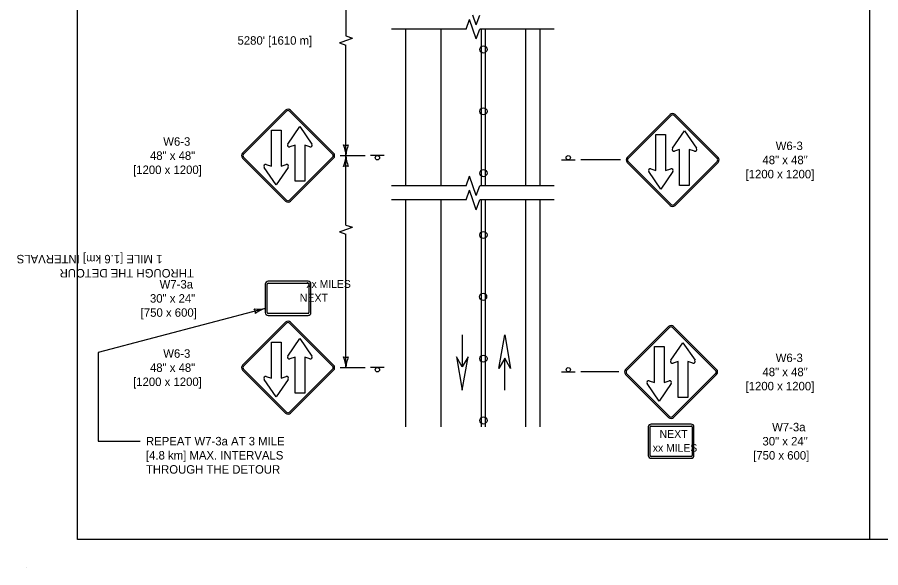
# Model space of a CAD drawing. Extents: x 49991.4 to 50021, y 49987.6 to 50011.4.
# Drawn here: x 49998.96 to 50005.06, y 49987.6 to 49991.49 of the extents above; entities that cross this region are included whole.
import ezdxf

# ---------------------------------------------------------------- set-up
doc = ezdxf.new("R2010")
doc.units = 0
for name, color, linetype in [('Level 1', 7, 'Continuous'), ('Level 2', 7, 'Continuous'), ('Level 3', 7, 'Continuous'), ('Level 6', 7, 'Continuous')]:
    doc.layers.add(name, color=color, linetype=linetype)

msp = doc.modelspace()

# ---------------------------------------------------------------- linework, layer by layer
at = {"layer": 'Level 1'}
for p, q in [((50001.7052, 49990.3007), (50001.7052, 49991.4092)), ((50001.9552, 49990.3007), (50001.9552, 49991.4092)), ((50002.2402, 49990.3007), (50002.2402, 49991.4092)), ((50002.2702, 49990.3007), (50002.2702, 49991.4092)), ((50002.5552, 49990.3007), (50002.5552, 49991.4092)), ((50002.6552, 49990.3007), (50002.6552, 49991.4092)), ((50000.5513, 49990.532), (50000.8555, 49990.836)), ((50000.5585, 49990.5248), (50000.8625, 49990.829)), ((50000.8837, 49990.829), (50001.1877, 49990.5248)), ((50000.8909, 49990.836), (50001.1949, 49990.532)), ((50003.271, 49990.5017), (50003.575, 49990.8057)), ((50003.2782, 49990.4947), (50003.5822, 49990.7987)), ((50003.6034, 49990.7987), (50003.9074, 49990.4947)), ((50003.6104, 49990.8057), (50003.9146, 49990.5017)), ((50000.7553, 49990.695), (50000.8233, 49990.695)), ((50000.7553, 49990.4396), (50000.7553, 49990.695)), ((50000.8233, 49990.695), (50000.8233, 49990.4396)), ((50000.8717, 49990.5968), (50000.9569, 49990.7206)), ((50000.9569, 49990.7206), (50001.0421, 49990.5968)), ((50003.5914, 49990.5667), (50003.6766, 49990.6903)), ((50003.6766, 49990.6903), (50003.7616, 49990.5667)), ((50003.475, 49990.4091), (50003.475, 49990.6647)), ((50003.475, 49990.6647), (50003.543, 49990.6647)), ((50003.543, 49990.6647), (50003.543, 49990.4091)), ((50000.9229, 49990.5892), (50000.8865, 49990.5772)), ((50000.9229, 49990.3336), (50000.9229, 49990.5892)), ((50001.0273, 49990.5772), (50000.9909, 49990.5892)), ((50000.9909, 49990.5892), (50000.9909, 49990.3336)), ((50001.5532, 49990.5144), (50001.4572, 49990.5144)), ((50003.6426, 49990.5587), (50003.6062, 49990.5471)), ((50003.6426, 49990.3033), (50003.6426, 49990.5587)), ((50003.747, 49990.5471), (50003.7106, 49990.5587)), ((50003.7106, 49990.5587), (50003.7106, 49990.3033)), ((50000.8555, 49990.1926), (50000.5513, 49990.4966)), ((50000.8625, 49990.1996), (50000.5585, 49990.5036)), ((50000.7189, 49990.4512), (50000.7553, 49990.4396)), ((50000.8233, 49990.4396), (50000.8597, 49990.4512)), ((50001.1877, 49990.5036), (50000.8837, 49990.1996)), ((50001.1949, 49990.4966), (50000.8909, 49990.1926)), ((50002.8071, 49990.4839), (50002.9031, 49990.4839)), ((50003.575, 49990.1623), (50003.271, 49990.4663)), ((50003.5822, 49990.1693), (50003.2782, 49990.4735)), ((50003.9074, 49990.4735), (50003.6034, 49990.1693)), ((50003.9146, 49990.4663), (50003.6104, 49990.1623)), ((50000.7893, 49990.308), (50000.7043, 49990.4316)), ((50000.8745, 49990.4316), (50000.7893, 49990.308)), ((50003.509, 49990.2777), (50003.4238, 49990.4015)), ((50003.4386, 49990.4211), (50003.475, 49990.4091)), ((50003.5942, 49990.4015), (50003.509, 49990.2777)), ((50003.543, 49990.4091), (50003.5794, 49990.4211)), ((50000.9909, 49990.3336), (50000.9229, 49990.3336)), ((50003.7106, 49990.3033), (50003.6426, 49990.3033)), ((50001.7052, 49988.5963), (50001.7052, 49990.2007)), ((50001.9552, 49988.5963), (50001.9552, 49990.2007)), ((50002.2402, 49988.5963), (50002.2402, 49990.2007)), ((50002.2702, 49988.5963), (50002.2702, 49990.2007)), ((50002.5552, 49988.5963), (50002.5552, 49990.2007)), ((50002.6552, 49988.5963), (50002.6552, 49990.2007)), ((50000.7118, 49989.6053), (50000.7118, 49989.4037)), ((50000.7253, 49989.4037), (50000.7253, 49989.6053)), ((50001.0143, 49989.6254), (50000.732, 49989.6254)), ((50000.732, 49989.612), (50001.0143, 49989.612)), ((50001.021, 49989.6053), (50001.021, 49989.4037)), ((50001.0344, 49989.4037), (50001.0344, 49989.6053)), ((50001.0143, 49989.3969), (50000.732, 49989.3969)), ((50000.732, 49989.3835), (50001.0143, 49989.3835)), ((50000.5513, 49989.032), (50000.8555, 49989.336)), ((50000.5585, 49989.0248), (50000.8625, 49989.329)), ((50000.8837, 49989.329), (50001.1877, 49989.0248)), ((50000.8909, 49989.336), (50001.1949, 49989.032)), ((50003.2605, 49989.0018), (50003.5645, 49989.3058)), ((50003.2677, 49988.9948), (50003.5717, 49989.2988)), ((50003.5929, 49989.2988), (50003.8969, 49988.9948)), ((50003.5999, 49989.3058), (50003.9041, 49989.0018)), ((50002.1052, 49989.2456), (50002.1052, 49989.0198)), ((50002.1054, 49989.2456), (50002.1054, 49989.0198)), ((50000.7553, 49989.195), (50000.8233, 49989.195)), ((50000.7553, 49988.9396), (50000.7553, 49989.195)), ((50000.8233, 49989.195), (50000.8233, 49988.9396)), ((50000.8717, 49989.0968), (50000.9569, 49989.2206)), ((50000.9569, 49989.2206), (50001.0421, 49989.0968)), ((50003.4645, 49988.9092), (50003.4645, 49989.1648)), ((50003.4645, 49989.1648), (50003.5325, 49989.1648)), ((50003.5325, 49989.1648), (50003.5325, 49988.9092)), ((50003.5809, 49989.0668), (50003.6661, 49989.1904)), ((50003.6661, 49989.1904), (50003.7511, 49989.0668)), ((50000.9229, 49989.0892), (50000.8865, 49989.0772)), ((50000.9229, 49988.8336), (50000.9229, 49989.0892)), ((50001.0273, 49989.0772), (50000.9909, 49989.0892)), ((50000.9909, 49989.0892), (50000.9909, 49988.8336)), ((50002.4051, 49988.8556), (50002.4051, 49989.0814)), ((50002.4053, 49988.8556), (50002.4053, 49989.0814)), ((50003.6321, 49989.0588), (50003.5957, 49989.0472)), ((50003.6321, 49988.8034), (50003.6321, 49989.0588)), ((50003.7365, 49989.0472), (50003.7001, 49989.0588)), ((50003.7001, 49989.0588), (50003.7001, 49988.8034)), ((50000.8555, 49988.6926), (50000.5513, 49988.9966)), ((50000.8625, 49988.6996), (50000.5585, 49989.0036)), ((50001.1877, 49989.0036), (50000.8837, 49988.6996)), ((50001.1949, 49988.9966), (50000.8909, 49988.6926)), ((50001.5532, 49989.0144), (50001.4572, 49989.0144)), ((50002.8072, 49988.984), (50002.9032, 49988.984)), ((50000.7893, 49988.808), (50000.7043, 49988.9316)), ((50000.7189, 49988.9512), (50000.7553, 49988.9396)), ((50000.8745, 49988.9316), (50000.7893, 49988.808)), ((50000.8233, 49988.9396), (50000.8597, 49988.9512)), ((50003.5645, 49988.6624), (50003.2605, 49988.9664)), ((50003.5717, 49988.6694), (50003.2677, 49988.9736)), ((50003.4281, 49988.9212), (50003.4645, 49988.9092)), ((50003.5325, 49988.9092), (50003.5689, 49988.9212)), ((50003.8969, 49988.9736), (50003.5929, 49988.6694)), ((50003.9041, 49988.9664), (50003.5999, 49988.6624)), ((50003.4985, 49988.7778), (50003.4133, 49988.9016)), ((50003.5837, 49988.9016), (50003.4985, 49988.7778)), ((50000.9909, 49988.8336), (50000.9229, 49988.8336)), ((50003.7001, 49988.8034), (50003.6321, 49988.8034)), ((50003.7234, 49988.615), (50003.4411, 49988.615)), ((50003.4209, 49988.5948), (50003.4209, 49988.3932)), ((50003.4344, 49988.3932), (50003.4344, 49988.5948)), ((50003.4411, 49988.6015), (50003.7234, 49988.6015)), ((50003.7301, 49988.5948), (50003.7301, 49988.3932)), ((50003.7435, 49988.3932), (50003.7435, 49988.5948)), ((50003.7234, 49988.3865), (50003.4411, 49988.3865)), ((50003.4411, 49988.3731), (50003.7234, 49988.3731)), ((49999.0245, 49987.5988), (49999.0245, 49987.5988))]:
    msp.add_line(p, q, dxfattribs=at)
for points in [[(49999.3835, 49998.9992), (50016.7501, 49998.9992), (50016.7501, 49987.7988), (49999.3835, 49987.7988)], [(50002.3633, 49989.0092), (50002.4051, 49989.2456), (50002.4469, 49989.0092), (50002.4051, 49989.0812)], [(50002.0634, 49989.092), (50002.1052, 49988.8556), (50002.147, 49989.092), (50002.1052, 49989.02)]]:
    msp.add_lwpolyline(points, close=True, dxfattribs=at)
for centre, radius in [((50002.255, 49991.2657), 0.025), ((50002.255, 49990.8282), 0.025), ((50001.5052, 49990.4992), 0.0152), ((50002.855, 49990.4993), 0.0152), ((50002.255, 49990.3907), 0.025), ((50002.255, 49989.9532), 0.025), ((50002.2524, 49989.5157), 0.025), ((50002.255, 49989.0782), 0.025), ((50001.5052, 49988.9992), 0.0152), ((50002.8552, 49988.9992), 0.0152), ((50002.255, 49988.6407), 0.025), ((50002.255, 49988.6407), 0.025)]:
    msp.add_circle(centre, radius, dxfattribs=at)
for centre, radius, start, end in [((50000.8731, 49990.8185), 0.025, 45.00043, 135), ((50000.8731, 49990.8185), 0.015, 45.00043, 135), ((50003.5927, 49990.788), 0.025, 45, 135), ((50003.5927, 49990.788), 0.015, 45, 135), ((50000.8825, 49990.5897), 0.0129, 145.58495, 216.71634), ((50000.8825, 49990.5897), 0.0129, 216.71939, 287.95818), ((50001.0313, 49990.5897), 0.0129, 252.04182, 323.27756), ((50001.0313, 49990.5897), 0.0129, 323.28061, 34.51941), ((50000.5691, 49990.5144), 0.025, 135, 225), ((50000.5691, 49990.5144), 0.015, 135, 225), ((50001.1772, 49990.5144), 0.015, 314.99976, 45), ((50001.1772, 49990.5144), 0.025, 314.99976, 45), ((50003.6021, 49990.5592), 0.0129, 145.58495, 216.71634), ((50003.6021, 49990.5592), 0.0129, 216.71939, 287.95818), ((50003.7509, 49990.5592), 0.0129, 252.04182, 323.27756), ((50003.7509, 49990.5592), 0.0129, 323.28061, 34.51941), ((50000.7149, 49990.4392), 0.0129, 143.28061, 214.51941), ((50000.7149, 49990.4392), 0.0129, 72.04182, 143.27756), ((50000.8638, 49990.4392), 0.0129, 36.71939, 107.95818), ((50000.8638, 49990.4392), 0.0129, 325.58495, 36.71634), ((50003.2887, 49990.4839), 0.025, 134.99976, 225), ((50003.2887, 49990.4839), 0.015, 134.99976, 225), ((50003.8968, 49990.4839), 0.015, 315, 45), ((50003.8968, 49990.4839), 0.025, 315, 45), ((50003.4345, 49990.4087), 0.0129, 143.28061, 214.51941), ((50003.4345, 49990.4087), 0.0129, 72.04182, 143.27756), ((50003.5834, 49990.4087), 0.0129, 36.71939, 107.95818), ((50003.5834, 49990.4087), 0.0129, 325.58495, 36.71634), ((50000.8731, 49990.2104), 0.025, 225, 315), ((50000.8731, 49990.2104), 0.015, 225, 315), ((50003.5927, 49990.1799), 0.025, 225.00043, 315), ((50003.5927, 49990.1799), 0.015, 225.00043, 315), ((50000.732, 49989.6053), 0.0202, 90, 180), ((50000.732, 49989.6053), 0.00672, 90, 180), ((50001.0143, 49989.6053), 0.0202, 360, 90), ((50001.0143, 49989.6053), 0.00672, 360, 90), ((50000.732, 49989.4037), 0.0202, 180, 270), ((50000.732, 49989.4037), 0.00672, 180, 270), ((50001.0143, 49989.4037), 0.00672, 270, 360), ((50001.0143, 49989.4037), 0.0202, 270, 360), ((50000.8731, 49989.3185), 0.025, 45.00043, 135), ((50000.8731, 49989.3185), 0.015, 45.00043, 135), ((50003.5822, 49989.2881), 0.025, 45, 135), ((50003.5822, 49989.2881), 0.015, 45, 135), ((50000.8825, 49989.0897), 0.0129, 145.58495, 216.71634), ((50000.8825, 49989.0897), 0.0129, 216.71939, 287.95818), ((50001.0313, 49989.0897), 0.0129, 252.04182, 323.27756), ((50001.0313, 49989.0897), 0.0129, 323.28061, 34.51941), ((50003.5916, 49989.0593), 0.0129, 145.58495, 216.71634), ((50003.5916, 49989.0593), 0.0129, 216.71939, 287.95818), ((50003.7404, 49989.0593), 0.0129, 252.04182, 323.27756), ((50003.7404, 49989.0593), 0.0129, 323.28061, 34.51941), ((50000.5691, 49989.0144), 0.025, 135, 225), ((50000.5691, 49989.0144), 0.015, 135, 225), ((50001.1772, 49989.0144), 0.015, 314.99976, 45), ((50001.1772, 49989.0144), 0.025, 314.99976, 45), ((50003.2782, 49988.984), 0.025, 134.99976, 225), ((50003.2782, 49988.984), 0.015, 134.99976, 225), ((50003.8863, 49988.984), 0.015, 315, 45), ((50003.8863, 49988.984), 0.025, 315, 45), ((50000.7149, 49988.9392), 0.0129, 143.28061, 214.51941), ((50000.7149, 49988.9392), 0.0129, 72.04182, 143.27756), ((50000.8638, 49988.9392), 0.0129, 36.71939, 107.95818), ((50000.8638, 49988.9392), 0.0129, 325.58495, 36.71634), ((50003.424, 49988.9088), 0.0129, 72.04182, 143.27756), ((50003.5729, 49988.9088), 0.0129, 36.71939, 107.95818), ((50003.424, 49988.9088), 0.0129, 143.28061, 214.51941), ((50003.5729, 49988.9088), 0.0129, 325.58495, 36.71634), ((50000.8731, 49988.7104), 0.025, 225, 315), ((50000.8731, 49988.7104), 0.015, 225, 315), ((50003.4411, 49988.5948), 0.0202, 90, 180), ((50003.5822, 49988.68), 0.025, 225.00043, 315), ((50003.5822, 49988.68), 0.015, 225.00043, 315), ((50003.7234, 49988.5948), 0.0202, 0, 90), ((50003.4411, 49988.5948), 0.00672, 90, 180), ((50003.7234, 49988.5948), 0.00672, 0, 90), ((50003.4411, 49988.3932), 0.0202, 180, 270), ((50003.4411, 49988.3932), 0.00672, 180, 270), ((50003.7234, 49988.3932), 0.0202, 270, 360), ((50003.7234, 49988.3932), 0.00672, 270, 360)]:
    msp.add_arc(centre, radius, start, end, dxfattribs=at)
at = {"layer": 'Level 3'}
for p, q in [((50004.9877, 49987.7988), (50004.9877, 49998.9992)), ((50001.2822, 49992.2283), (50001.2822, 49991.3619)), ((50001.2822, 49991.3619), (50001.3279, 49991.3457)), ((50001.2365, 49991.3133), (50001.2822, 49991.3295)), ((50001.2365, 49991.3133), (50001.2822, 49991.2971)), ((50001.2822, 49991.3295), (50001.3279, 49991.3457)), ((50001.2822, 49990.5144), (50001.2822, 49991.2971)), ((50001.2422, 49990.5144), (50001.4172, 49990.5144)), ((50001.2822, 49990.0238), (50001.2822, 49990.5144)), ((50003.2237, 49990.4839), (50002.9431, 49990.4839)), ((50001.2822, 49990.0238), (50001.3279, 49990.0076)), ((50001.2365, 49989.9752), (50001.2822, 49989.9914)), ((50001.2365, 49989.9752), (50001.2822, 49989.959)), ((50001.2822, 49989.9914), (50001.3279, 49990.0076)), ((50001.2822, 49989.0144), (50001.2822, 49989.959)), ((50000.7118, 49989.4339), (49999.5311, 49989.121)), ((49999.5311, 49989.121), (49999.5311, 49988.4944)), ((50001.2422, 49989.0144), (50001.4172, 49989.0144)), ((50003.2132, 49988.984), (50002.9432, 49988.984)), ((49999.5311, 49988.4944), (49999.8279, 49988.4944))]:
    msp.add_line(p, q, dxfattribs=at)
for centre, radius, start, end in [((50001.2822, 49990.6427), 0.0548, 252.13882, 287.86118), ((50001.0495, 49990.5029), 0.233, 2.82731, 22.07716), ((50001.5043, 49990.5053), 0.2223, 157.45601, 177.63952), ((50001.0601, 49990.5236), 0.2223, 337.45601, 357.63952), ((50001.5149, 49990.5259), 0.233, 182.82731, 202.07716), ((50001.2822, 49990.3862), 0.0548, 72.13882, 107.86118), ((50000.6638, 49989.651), 0.2223, 262.30052, 282.48403), ((50000.5879, 49989.4011), 0.0548, 356.98333, 32.70569), ((50000.7826, 49989.2119), 0.233, 107.67182, 126.92167), ((50001.2822, 49989.1427), 0.0548, 252.13882, 287.86118), ((50001.0495, 49989.0029), 0.233, 2.82731, 22.07716), ((50001.5043, 49989.0053), 0.2223, 157.45601, 177.63952)]:
    msp.add_arc(centre, radius, start, end, dxfattribs=at)
at = {"layer": 'Level 6'}
for p, q in [((50002.2044, 49991.4408), (50002.1802, 49991.5092)), ((50002.2044, 49991.4408), (50002.2288, 49991.5092)), ((50002.1316, 49991.4092), (50002.156, 49991.478)), ((50002.1802, 49991.4092), (50002.156, 49991.478)), ((50002.1316, 49991.4092), (50001.6052, 49991.4092)), ((50002.2044, 49991.3408), (50002.1802, 49991.4092)), ((50002.2044, 49991.3408), (50002.2288, 49991.4092)), ((50002.7552, 49991.4092), (50002.2288, 49991.4092)), ((50002.1316, 49990.3007), (50002.156, 49990.3695)), ((50002.1802, 49990.3007), (50002.156, 49990.3695)), ((50002.1316, 49990.3007), (50001.6052, 49990.3007)), ((50002.1316, 49990.2007), (50002.156, 49990.2695)), ((50002.1802, 49990.2007), (50002.156, 49990.2695)), ((50002.2044, 49990.2323), (50002.1802, 49990.3007)), ((50002.2044, 49990.2323), (50002.2288, 49990.3007)), ((50002.7552, 49990.3007), (50002.2288, 49990.3007)), ((50002.1316, 49990.2007), (50001.6052, 49990.2007)), ((50002.2044, 49990.1323), (50002.1802, 49990.2007)), ((50002.2044, 49990.1323), (50002.2288, 49990.2007)), ((50002.7552, 49990.2007), (50002.2288, 49990.2007))]:
    msp.add_line(p, q, dxfattribs=at)

# ---------------------------------------------------------------- texts
at = {"layer": 'Level 1'}
for s, height, p in [('xx MILES', 0.05493, (50001.0026, 49989.579)), ('NEXT', 0.05599, (50000.9556, 49989.4809))]:
    msp.add_text(s, height=height, rotation=360, dxfattribs=at).set_placement(p)
for s, height, p in [('NEXT', 0.05599, (50003.4997, 49988.5176)), ('xx MILES', 0.05493, (50003.4527, 49988.4195))]:
    msp.add_text(s, height=height, dxfattribs=at).set_placement(p)
at = {"layer": 'Level 2'}
for s, p in [("5280' [1610 m]", (50000.5154, 49991.2995)), ('W6-3', (49999.9901, 49990.5845)), ('W6-3', (50004.3219, 49990.554)), ('48" x 48"', (49999.8963, 49990.4845)), ('48" x 48"', (50004.2281, 49990.454)), ('[1200 x 1200]', (49999.7769, 49990.3845)), ('[1200 x 1200]', (50004.1087, 49990.354)), ('W7-3a', (49999.9647, 49989.5745)), ('30" x 24"', (49999.8963, 49989.4745)), ('[750 x 600]', (49999.8307, 49989.3745)), ('W6-3', (49999.9901, 49989.0844)), ('W6-3', (50004.3219, 49989.054)), ('48" x 48"', (49999.8963, 49988.9844)), ('48" x 48"', (50004.2281, 49988.954)), ('[1200 x 1200]', (49999.7769, 49988.8844)), ('[1200 x 1200]', (50004.1087, 49988.854)), ('W7-3a', (50004.2965, 49988.564)), ('REPEAT W7-3a AT 3 MILE  ', (49999.8679, 49988.4644)), ('30" x 24"', (50004.2281, 49988.464)), ('[4.8 km] MAX. INTERVALS ', (49999.8679, 49988.3644)), ('[750 x 600]', (50004.1625, 49988.364)), ('THROUGH THE DETOUR', (49999.8679, 49988.2644))]:
    msp.add_text(s, height=0.06, dxfattribs=at).set_placement(p)
for s, p in [('1 MILE [1.6 km] INTERVALS', (49999.9841, 49989.8124)), ('THROUGH THE DETOUR', (50000.2066, 49989.7124))]:
    msp.add_text(s, height=0.06, rotation=180, dxfattribs=at).set_placement(p)

doc.saveas('drawing.dxf')
